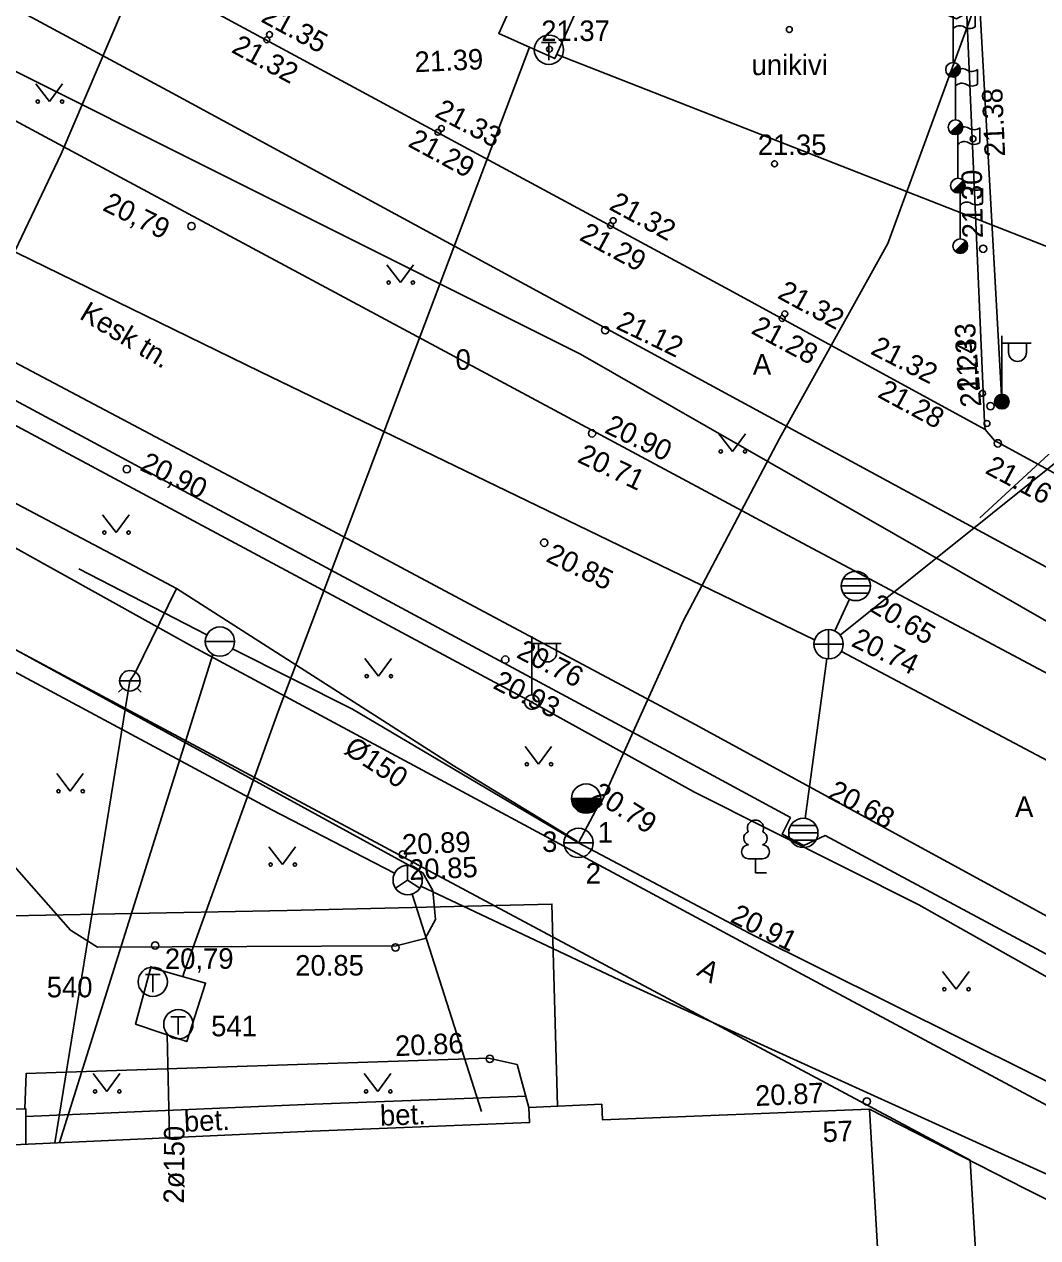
# Model space of a CAD drawing. Extents: x 714038 to 714279, y 6589845 to 6590041.
# Drawn here: x 714214.57 to 714249.16, y 6589892.78 to 6589934.18 of the extents above; entities that cross this region are included whole.
import ezdxf

# ---------------------------------------------------------------- set-up
doc = ezdxf.new("R2010")
doc.units = 0
for name, color, linetype in [('HALJASTUS', 7, 'Continuous'), ('HOONE', 7, 'Continuous'), ('HOONEDET', 7, 'Continuous'), ('KKAEV', 7, 'Continuous'), ('KORGUS', 7, 'Continuous'), ('KPKAABEL', 7, 'Continuous'), ('MPKAABEL', 7, 'Continuous'), ('POST', 7, 'Continuous'), ('PUU', 7, 'Continuous'), ('RAJATIS', 7, 'Continuous'), ('SIKAEV', 7, 'Continuous'), ('SITRASS', 7, 'Continuous'), ('SKKAEV', 7, 'Continuous'), ('SKTRASS', 7, 'Continuous'), ('TEE', 7, 'Continuous'), ('TKAEV', 7, 'Continuous'), ('TORU NR', 7, 'Continuous'), ('TTRASS', 7, 'Continuous'), ('VKAEV', 7, 'Continuous'), ('VTRASS', 7, 'Continuous'), ('Слой 1', 7, 'Continuous')]:
    doc.layers.add(name, color=color, linetype=linetype)

msp = doc.modelspace()

# ---------------------------------------------------------------- linework, layer by layer
at = {"layer": 'HALJASTUS'}
for p, q in [((714214.971, 6589932.147), (714215.434, 6589931.54)), ((714215.434, 6589931.54), (714215.88, 6589932.147)), ((714226.945, 6589925.973), (714227.409, 6589925.366)), ((714227.409, 6589925.366), (714227.854, 6589925.973)), ((714238.28, 6589920.21), (714238.744, 6589919.603)), ((714238.744, 6589919.603), (714239.189, 6589920.21)), ((714217.242, 6589917.442), (714217.706, 6589916.836)), ((714217.706, 6589916.836), (714218.151, 6589917.442)), ((714226.198, 6589912.544), (714226.661, 6589911.937)), ((714226.661, 6589911.937), (714227.107, 6589912.544)), ((714231.662, 6589909.537), (714232.126, 6589908.931)), ((714232.126, 6589908.931), (714232.571, 6589909.537)), ((714215.678, 6589908.619), (714216.141, 6589908.012)), ((714216.141, 6589908.012), (714216.587, 6589908.619)), ((714222.917, 6589906.115), (714223.381, 6589905.508)), ((714223.381, 6589905.508), (714223.826, 6589906.115)), ((714245.911, 6589901.864), (714246.374, 6589901.257)), ((714246.374, 6589901.257), (714246.819, 6589901.864)), ((714216.927, 6589898.377), (714217.39, 6589897.77)), ((714217.39, 6589897.77), (714217.836, 6589898.377)), ((714226.176, 6589898.377), (714226.64, 6589897.77)), ((714226.64, 6589897.77), (714227.085, 6589898.377))]:
    msp.add_line(p, q, dxfattribs=at)
for centre in [(714215.033, 6589931.54), (714215.862, 6589931.54), (714227.008, 6589925.366), (714227.837, 6589925.366), (714238.343, 6589919.603), (714239.172, 6589919.603), (714217.305, 6589916.836), (714218.133, 6589916.836), (714226.26, 6589911.937), (714227.089, 6589911.937), (714231.725, 6589908.931), (714232.554, 6589908.931), (714215.74, 6589908.012), (714216.569, 6589908.012), (714222.98, 6589905.508), (714223.808, 6589905.508), (714245.973, 6589901.257), (714246.802, 6589901.257), (714216.989, 6589897.77), (714217.818, 6589897.77), (714226.239, 6589897.77), (714227.067, 6589897.77)]:
    msp.add_circle(centre, 0.055, dxfattribs=at)
at = {"layer": 'HOONE'}
for points in [[(714037.81, 6590017.576), (714059.08, 6590006.51), (714072.38, 6589999.69), (714082.14, 6589994.37), (714104.85, 6589981.96), (714150.21, 6589957.43), (714183.55, 6589939.45), (714202.68, 6589928.99), (714214.04, 6589922.75), (714222.92, 6589918.06), (714237.47, 6589910.29), (714252.27, 6589902.23), (714256.602, 6589899.815), (714258.577, 6589898.715), (714261.69, 6589896.98)], [(714232.775, 6589897.266), (714232.58, 6589904.16), (714223.55, 6589903.94), (714211.77, 6589903.72), (714206.52, 6589903.61), (714195.92, 6589923.31), (714175.53, 6589922.39), (714175.7, 6589917.845), (714175.811, 6589914.882), (714176.08, 6589907.69)], [(714224.4, 6589896.416), (714231.818, 6589896.708), (714231.798, 6589897.222), (714234.283, 6589897.334), (714234.304, 6589896.805), (714243.421, 6589897.164), (714244.031, 6589886.542), (714224.36, 6589885.65), (714203.25, 6589884.69), (714202.77, 6589895.43), (714224.4, 6589896.416)]]:
    msp.add_lwpolyline(points, dxfattribs=at)
at = {"layer": 'HOONEDET'}
for points in [[(714214.63, 6589896.91), (714224.16, 6589897.321), (714231.692, 6589897.611)], [(714214.63, 6589895.98), (714214.63, 6589897.17), (714211.6, 6589897.12), (714211.69, 6589895.84)]]:
    msp.add_lwpolyline(points, dxfattribs=at)
at = {"layer": 'KKAEV'}
for p, q in [((714242.025, 6589912.527), (714242.025, 6589913.527)), ((714241.525, 6589913.027), (714242.525, 6589913.027))]:
    msp.add_line(p, q, dxfattribs=at)
msp.add_circle((714242.025, 6589913.027), 0.5, dxfattribs=at)
at = {"layer": 'KORGUS'}
for centre, radius in [((714240.683, 6589933.996), 0.1), ((714222.849, 6589933.644), 0.1), ((714222.94, 6589933.825), 0.1), ((714232.5, 6589933.327), 0.1), ((714228.808, 6589930.621), 0.1), ((714228.692, 6589930.492), 0.1), ((714246.953, 6589930.268), 0.1), ((714240.179, 6589929.419), 0.1), ((714220.28, 6589927.29), 0.125), ((714234.583, 6589927.315), 0.1), ((714234.674, 6589927.477), 0.1), ((714247.3, 6589926.52), 0.125), ((714240.437, 6589924.138), 0.1), ((714240.528, 6589924.3), 0.1), ((714234.4, 6589923.74), 0.125), ((714247.279, 6589921.586), 0.1), ((714247.55, 6589921.15), 0.125), ((714247.429, 6589920.558), 0.1), ((714233.95, 6589920.22), 0.125), ((714247.8, 6589919.88), 0.125), ((714218.07, 6589919), 0.125), ((714232.32, 6589916.49), 0.125), ((714230.99, 6589912.5), 0.125), ((714227.49, 6589905.85), 0.125), ((714219.04, 6589902.75), 0.125), ((714227.24, 6589902.68), 0.125), ((714230.46, 6589898.88), 0.125), ((714243.33, 6589897.43), 0.125)]:
    msp.add_circle(centre, radius, dxfattribs=at)
at = {"layer": 'KPKAABEL'}
msp.add_lwpolyline([(714278.95, 6590013.083), (714274.696, 6590002.154), (714268.806, 6589986.746), (714264.689, 6589977.209), (714260.118, 6589965.851), (714258.032, 6589961.24), (714253.05, 6589949.372), (714248.466, 6589938.096), (714247.531, 6589934.989), (714246.389, 6589934.367), (714239.483, 6589937.254), (714226.492, 6589940.819), (714222.669, 6589940.979), (714220.982, 6589941.049), (714220.257, 6589940.365), (714218.76, 6589936.611), (714215.836, 6589929.757), (714212.225, 6589922.206), (714208.098, 6589916.26), (714202.344, 6589907.69)], dxfattribs=at)
at = {"layer": 'MPKAABEL'}
for points in [[(714167.029, 6589999.261), (714167.805, 6589985.535), (714167.801, 6589985.524), (714168.701, 6589969.69), (714168.856, 6589964.517), (714181.003, 6589963.765), (714182.873, 6589963.649), (714187.834, 6589963.342), (714201.122, 6589963.986), (714214.138, 6589964.636), (714217.634, 6589964.759), (714217.843, 6589958.743), (714218.335, 6589947.958), (714218.782, 6589937.076), (714219.871, 6589937.206), (714226.57, 6589937.936), (714228.214, 6589938.132), (714236.763, 6589938.683), (714246.845, 6589940.926), (714247.938, 6589921.303)], [(714215.066, 6589943.967), (714214.846, 6589942.32), (714213.494, 6589938.395), (714212.085, 6589935.688), (714211.383, 6589934.84), (714211.278, 6589934.105), (714212.162, 6589933.623), (714233.552, 6589922.923), (714249.701, 6589913.675), (714250.295, 6589914.005), (714250.521, 6589914.785), (714251.05, 6589918.335), (714251.513, 6589923.366), (714251.481, 6589924.441), (714250.114, 6589927.476), (714252.56, 6589933.122), (714254.403, 6589936.762), (714260.237, 6589952.896), (714261.787, 6589959.195)], [(714231.9, 6589911.052), (714205.454, 6589925.211)], [(714231.9, 6589911.052), (714237.45, 6589907.982), (714245.1, 6589904.132), (714257.12, 6589897.374), (714259.08, 6589896.4)]]:
    msp.add_lwpolyline(points, dxfattribs=at)
at = {"layer": 'POST'}
for p, q in [((714246.095, 6589932.449), (714246.449, 6589932.802)), ((714246.178, 6589930.486), (714246.532, 6589930.839)), ((714246.26, 6589928.497), (714246.614, 6589928.85)), ((714246.341, 6589926.432), (714246.695, 6589926.785)), ((714247.938, 6589921.553), (714247.938, 6589923.553)), ((714247.938, 6589923.303), (714248.938, 6589923.303)), ((714248.165, 6589922.982), (714248.165, 6589923.303)), ((714248.778, 6589922.982), (714248.778, 6589923.303)), ((714231.9, 6589911.302), (714231.9, 6589913.302)), ((714231.9, 6589913.052), (714232.9, 6589913.052)), ((714232.127, 6589912.731), (714232.127, 6589913.052)), ((714232.74, 6589912.731), (714232.74, 6589913.052))]:
    msp.add_line(p, q, dxfattribs=at)
for centre, radius in [((714246.272, 6589932.625), 0.25), ((714246.355, 6589930.662), 0.25), ((714246.437, 6589928.673), 0.25), ((714246.518, 6589926.608), 0.25), ((714247.938, 6589921.303), 0.25), ((714247.938, 6589921.303), 0.225), ((714247.938, 6589921.303), 0.2), ((714247.938, 6589921.303), 0.175), ((714247.938, 6589921.303), 0.15), ((714247.938, 6589921.303), 0.125), ((714247.938, 6589921.303), 0.1), ((714247.938, 6589921.303), 0.075), ((714247.938, 6589921.303), 0.05), ((714247.938, 6589921.303), 0.025), ((714231.9, 6589911.052), 0.25), ((714231.9, 6589911.052), 0.0234)]:
    msp.add_circle(centre, radius, dxfattribs=at)
for centre, radius, start, end in [((714246.272, 6589932.625), 0.225, 224.8541, 45.0356), ((714246.272, 6589932.625), 0.2, 224.8427, 45.047), ((714246.272, 6589932.625), 0.175, 224.8281, 45.0616), ((714246.272, 6589932.625), 0.15, 224.8087, 45.081), ((714246.272, 6589932.625), 0.125, 224.7814, 45.1083), ((714246.272, 6589932.625), 0.1, 224.7406, 45.1491), ((714246.272, 6589932.625), 0.075, 224.6725, 45.2172), ((714246.272, 6589932.625), 0.05, 224.5363, 45.3534), ((714246.272, 6589932.625), 0.025, 224.1278, 45.7619), ((714246.355, 6589930.662), 0.225, 224.8541, 45.0356), ((714246.355, 6589930.662), 0.2, 224.8427, 45.047), ((714246.355, 6589930.662), 0.175, 224.8281, 45.0616), ((714246.355, 6589930.662), 0.15, 224.8087, 45.081), ((714246.355, 6589930.662), 0.125, 224.7814, 45.1083), ((714246.355, 6589930.662), 0.1, 224.7406, 45.1491), ((714246.355, 6589930.662), 0.075, 224.6725, 45.2172), ((714246.355, 6589930.662), 0.05, 224.5363, 45.3534), ((714246.355, 6589930.662), 0.025, 224.1278, 45.7619), ((714246.437, 6589928.673), 0.225, 224.8541, 45.0356), ((714246.437, 6589928.673), 0.2, 224.8427, 45.047), ((714246.437, 6589928.673), 0.175, 224.8281, 45.0616), ((714246.437, 6589928.673), 0.15, 224.8087, 45.081), ((714246.437, 6589928.673), 0.125, 224.7814, 45.1083), ((714246.437, 6589928.673), 0.1, 224.7406, 45.1491), ((714246.437, 6589928.673), 0.075, 224.6725, 45.2172), ((714246.437, 6589928.673), 0.05, 224.5363, 45.3534), ((714246.437, 6589928.673), 0.025, 224.1278, 45.7619), ((714246.518, 6589926.608), 0.225, 224.8541, 45.0356), ((714246.518, 6589926.608), 0.2, 224.8427, 45.047), ((714246.518, 6589926.608), 0.175, 224.8281, 45.0616), ((714246.518, 6589926.608), 0.15, 224.8087, 45.081), ((714246.518, 6589926.608), 0.125, 224.7814, 45.1083), ((714246.518, 6589926.608), 0.1, 224.7406, 45.1491), ((714246.518, 6589926.608), 0.075, 224.6725, 45.2172), ((714246.518, 6589926.608), 0.05, 224.5363, 45.3534), ((714246.518, 6589926.608), 0.025, 224.1278, 45.7619), ((714248.471, 6589922.982), 0.306, 180, 0), ((714232.434, 6589912.731), 0.306, 180, 0)]:
    msp.add_arc(centre, radius, start, end, dxfattribs=at)
at = {"layer": 'PUU'}
for p, q in [((714239.768, 6589905.707), (714239.288, 6589905.707)), ((714239.528, 6589905.232), (714239.528, 6589905.707)), ((714239.908, 6589905.232), (714239.528, 6589905.232))]:
    msp.add_line(p, q, dxfattribs=at)
for centre, radius, start, end in [((714239.528, 6589906.752), 0.277, 332.5799, 207.4201), ((714239.358, 6589906.404), 0.233, 109.0217, 253.1415), ((714239.698, 6589906.404), 0.233, 286.8508, 70.9859), ((714239.29, 6589905.944), 0.238, 90.0016, 269.3953), ((714239.765, 6589905.944), 0.238, 270.6047, 89.9984)]:
    msp.add_arc(centre, radius, start, end, dxfattribs=at)
at = {"layer": 'RAJATIS'}
for p, q in [((714246.272, 6589932.875), (714246.272, 6589934.625)), ((714247.025, 6589934.594), (714247.025, 6589934.094)), ((714246.355, 6589930.912), (714246.355, 6589932.662)), ((714247.108, 6589932.631), (714247.108, 6589932.131)), ((714246.437, 6589928.923), (714246.437, 6589930.673)), ((714247.19, 6589930.642), (714247.19, 6589930.142)), ((714246.518, 6589926.858), (714246.518, 6589928.608)), ((714247.271, 6589928.577), (714247.271, 6589928.077))]:
    msp.add_line(p, q, dxfattribs=at)
msp.add_lwpolyline([(714231.588, 6589935.687), (714233.5, 6589934.828), (714232.68, 6589933.004), (714230.768, 6589933.863)], close=True, dxfattribs=at)
for centre, radius, start, end in [((714246.495, 6589933.841), 0.288, 57.8941, 140.7366), ((714246.829, 6589934.373), 0.341, 237.8941, 305.0219), ((714246.578, 6589932.378), 0.288, 57.8941, 140.7366), ((714246.912, 6589932.91), 0.341, 237.8941, 305.0219), ((714246.578, 6589931.878), 0.288, 57.8941, 140.7366), ((714246.912, 6589932.41), 0.341, 237.8941, 305.0219), ((714246.66, 6589930.389), 0.288, 57.8941, 140.7366), ((714246.994, 6589930.921), 0.341, 237.8941, 305.0219), ((714246.66, 6589929.889), 0.288, 57.8941, 140.7366), ((714246.994, 6589930.421), 0.341, 237.8941, 305.0219), ((714246.741, 6589928.324), 0.288, 57.8941, 140.7366), ((714247.076, 6589928.856), 0.341, 237.8941, 305.0219), ((714246.741, 6589927.824), 0.288, 57.8941, 140.7366), ((714247.076, 6589928.356), 0.341, 237.8941, 305.0219)]:
    msp.add_arc(centre, radius, start, end, dxfattribs=at)
at = {"layer": 'SIKAEV'}
for p, q in [((714227.657, 6589905.482), (714227.657, 6589904.982)), ((714227.657, 6589904.982), (714227.242, 6589904.707)), ((714227.657, 6589904.982), (714228.072, 6589904.707))]:
    msp.add_line(p, q, dxfattribs=at)
msp.add_circle((714227.657, 6589904.982), 0.5, dxfattribs=at)
at = {"layer": 'SITRASS'}
for points in [[(714227.213, 6589905.211), (714223.017, 6589907.372), (714207.091, 6589915.92), (714188.911, 6589925.93), (714174.372, 6589933.714)], [(714228.11, 6589904.769), (714235.097, 6589901.472), (714246.809, 6589896.155), (714249.743, 6589894.816), (714250.57, 6589894.44), (714264.7, 6589888.06), (714272.32, 6589884.65)], [(714227.809, 6589904.505), (714230.172, 6589897.083)]]:
    msp.add_lwpolyline(points, dxfattribs=at)
at = {"layer": 'SKKAEV'}
for p, q in [((714242.453, 6589915.013), (714243.453, 6589915.013)), ((714243.383, 6589915.263), (714242.523, 6589915.263)), ((714243.383, 6589914.763), (714242.523, 6589914.763)), ((714241.591, 6589906.84), (714240.731, 6589906.84)), ((714240.661, 6589906.59), (714241.661, 6589906.59)), ((714241.591, 6589906.34), (714240.731, 6589906.34))]:
    msp.add_line(p, q, dxfattribs=at)
for centre in [(714242.953, 6589915.013), (714241.161, 6589906.59)]:
    msp.add_circle(centre, 0.5, dxfattribs=at)
at = {"layer": 'SKTRASS'}
for points in [[(714242.415, 6589913.339), (714255.39, 6589923.72), (714264.171, 6589931.743)], [(714204.551, 6589931.144), (714222.61, 6589922.33), (714241.548, 6589913.176), (714241.548, 6589913.176)], [(714247.18, 6589917.34), (714253.06, 6589922.75), (714259.876, 6589929.158)], [(714242.741, 6589914.56), (714242.237, 6589913.48)], [(714241.958, 6589912.531), (714241.228, 6589907.086)], [(714278.95, 6589894.02), (714269.47, 6589898.47), (714242.461, 6589912.782)]]:
    msp.add_lwpolyline(points, dxfattribs=at)
at = {"layer": 'TEE'}
for points in [[(714263.275, 6589906.612), (714262.481, 6589906.156), (714261.368, 6589906.05), (714260.213, 6589906.315), (714240.788, 6589916.652), (714217.995, 6589928.881), (714199.241, 6589938.974), (714197.452, 6589940.713), (714195.768, 6589942.431), (714184.455, 6589948.554)], [(714263.275, 6589906.612), (714263.414, 6589907.94), (714262.577, 6589908.551), (714241.037, 6589920.211), (714219.611, 6589931.838), (714198.955, 6589942.945), (714197.611, 6589943.352), (714197.847, 6589943.789), (714196.868, 6589944.026)], [(714217.759, 6589936.392), (714238.65, 6589925.109), (714247.372, 6589920.348), (714247.69, 6589919.978), (714264.11, 6589911.01), (714265.191, 6589911.398), (714265.199, 6589917.222), (714265.151, 6589925.259), (714246.63, 6589937.111), (714247.349, 6589920.604), (714247.372, 6589920.348)], [(714260.872, 6589896.331), (714241.905, 6589906.497), (714241.183, 6589906.16), (714240.441, 6589906.543), (714240.721, 6589907.111), (714236.852, 6589909.204), (714214.108, 6589921.428), (714203.766, 6589926.993), (714202.202, 6589927.469), (714201.413, 6589927.345), (714200.699, 6589926.934), (714199.125, 6589924.726), (714220.312, 6589912.945), (714241.895, 6589901.346), (714256.945, 6589893.296)], [(714228.18, 6589905.231), (714207.986, 6589916.277), (714199.093, 6589921.068), (714198.639, 6589920.168), (714199.213, 6589910.066), (714200.697, 6589907.311), (714202.103, 6589905.776), (714203.2, 6589905.324), (714213.313, 6589905.801), (714214.147, 6589905.548), (714216.152, 6589903.272), (714217.072, 6589902.693), (714227.265, 6589902.742), (714228.249, 6589902.983)], [(714228.249, 6589902.983), (714228.605, 6589903.639), (714228.517, 6589904.627), (714228.18, 6589905.231)], [(714214.59, 6589897.17), (714214.637, 6589898.38), (714230.412, 6589898.909), (714231.399, 6589898.684)], [(714231.399, 6589898.684), (714231.798, 6589897.222)], [(714263.472, 6589878.412), (714265.767, 6589878.509), (714265.522, 6589885.849), (714264.63, 6589886.315), (714264.168, 6589886.556), (714263.52, 6589886.894), (714261.567, 6589887.913), (714261.242, 6589888.082), (714254.879, 6589891.188), (714249.398, 6589894.111), (714248.724, 6589894.462), (714243.421, 6589897.164)]]:
    msp.add_lwpolyline(points, dxfattribs=at)
at = {"layer": 'TKAEV'}
for p, q in [((714232.228, 6589933.557), (714232.728, 6589933.557)), ((714232.478, 6589932.957), (714232.478, 6589933.557)), ((714218.71, 6589901.76), (714219.21, 6589901.76)), ((714218.96, 6589901.16), (714218.96, 6589901.76)), ((714219.58, 6589900.31), (714220.08, 6589900.31)), ((714219.83, 6589899.71), (714219.83, 6589900.31))]:
    msp.add_line(p, q, dxfattribs=at)
for centre in [(714232.478, 6589933.307), (714218.96, 6589901.51), (714219.83, 6589900.06)]:
    msp.add_circle(centre, 0.5, dxfattribs=at)
at = {"layer": 'TTRASS'}
for points in [[(714232.746, 6589933.149), (714263.03, 6589921.28), (714267.83, 6589934.38), (714270.013, 6589934.171), (714270.776, 6589934.097), (714278.95, 6589933.313)], [(714220.032, 6589901.833), (714223.24, 6589910.73), (714231.811, 6589933.394)], [(714218.89, 6589902), (714220.76, 6589901.46), (714220.12, 6589899.47), (714218.37, 6589900.06), (714218.9, 6589902.04)], [(714219.98, 6589901.69), (714220.032, 6589901.833)], [(714219.53, 6589896.2), (714219.45, 6589899.7)]]:
    msp.add_lwpolyline(points, dxfattribs=at)
at = {"layer": 'VKAEV'}
for p, q in [((714220.75, 6589913.116), (714221.75, 6589913.116)), ((714217.828, 6589911.78), (714218.528, 6589911.78)), ((714217.931, 6589911.533), (714217.791, 6589911.393)), ((714218.425, 6589911.533), (714218.565, 6589911.393)), ((714233.247, 6589907.759), (714234.247, 6589907.759)), ((714232.988, 6589906.247), (714233.988, 6589906.247))]:
    msp.add_line(p, q, dxfattribs=at)
for centre, radius in [((714221.25, 6589913.116), 0.5), ((714218.178, 6589911.78), 0.35), ((714233.747, 6589907.759), 0.5), ((714233.488, 6589906.247), 0.5)]:
    msp.add_circle(centre, radius, dxfattribs=at)
for radius in [0.483, 0.468, 0.45, 0.435, 0.418, 0.403, 0.386, 0.371, 0.354, 0.339, 0.321, 0.306, 0.289, 0.274, 0.257, 0.242, 0.224, 0.209, 0.192, 0.177, 0.16, 0.145, 0.127, 0.112, 0.0951, 0.0801, 0.0628, 0.0478, 0.0328, 0.0178]:
    msp.add_arc((714233.747, 6589907.759), radius, 180, 0, dxfattribs=at)
at = {"layer": 'VTRASS'}
for p, q in [((714218.178, 6589911.78), (714215.613, 6589896.015)), ((714234.193, 6589907.469), (714233.69, 6589907.777))]:
    msp.add_line(p, q, dxfattribs=at)
for points in [[(714234.193, 6589907.469), (714237.059, 6589913.816), (714240.349, 6589920.042), (714244.05, 6589926.694), (714247.419, 6589935.922), (714252.894, 6589948.5), (714258.093, 6589959.582), (714259.692, 6589963.065), (714262.845, 6589969.359)], [(714219.771, 6589914.924), (714218.336, 6589915.691), (714204.329, 6589923.078), (714196.383, 6589927.305), (714185.655, 6589933.263), (714178.705, 6589937.104), (714170.033, 6589941.737), (714162.674, 6589944.874), (714154.781, 6589949.135), (714153.798, 6589949.498)], [(714216.44, 6589915.593), (714220.805, 6589913.345)], [(714219.771, 6589914.924), (714218.362, 6589912.045), (714218.178, 6589911.78)], [(714219.771, 6589914.924), (714229.215, 6589908.89), (714233.438, 6589906.305)], [(714215.778, 6589896.023), (714221.01, 6589912.676), (714221.01, 6589912.677)], [(714221.682, 6589912.866), (714221.682, 6589912.866), (714225.77, 6589910.806), (714233.488, 6589906.247)], [(714233.747, 6589907.759), (714234.168, 6589907.537), (714233.488, 6589906.247)], [(714233.488, 6589906.247), (714239.337, 6589903.162), (714263.403, 6589891.181), (714275.749, 6589884.323), (714275.315, 6589880.416), (714276.224, 6589845.18)]]:
    msp.add_lwpolyline(points, dxfattribs=at)
at = {"layer": 'Слой 1'}
msp.add_lwpolyline([(714246.86, 6589895.42), (714247.69, 6589881.35), (714196.91, 6589879.78), (714193.95, 6589923.69)], close=True, dxfattribs=at)

# ---------------------------------------------------------------- texts
at = {"layer": 'HOONE'}
msp.add_text('57', height=0.7, rotation=2.582, dxfattribs=at).set_placement((714241.832, 6589896.035))
at = {"layer": 'HOONEDET'}
msp.add_text('bet.', height=0.7, rotation=2.2172, dxfattribs=at).set_placement((714226.725, 6589896.595))
at = {"layer": 'KORGUS'}
for s, rotation, p in [(' 21.35', 331.4612, (714222.384, 6589934.411)), (' 21.32', 331.6409, (714221.38, 6589933.362)), ('21.39', 2.5582, (714227.91, 6589932.54)), (' 21.38', 92.5441, (714248.064, 6589929.409)), (' 21.33', 332.1233, (714228.318, 6589931.165)), (' 21.29', 331.4894, (714227.404, 6589930.156)), ('21.30', 90.849, (714247.29, 6589926.88)), ('20,79', 334.0139, (714217.208, 6589927.847)), (' 21.32', 331.4871, (714234.266, 6589928.004)), (' 21.29', 331.5038, (714233.254, 6589926.958)), (' 21.32', 331.3647, (714240.015, 6589924.982)), ('21.12', 334.1771, (714234.73, 6589923.81)), (' 21.28', 331.7421, (714239.114, 6589923.775)), (' 21.33', 92.5441, (714247.139, 6589921.396)), (' 21.32', 332.8401, (714243.188, 6589923.068)), ('21.24', 94.6979, (714247.24, 6589921.14)), (' 21.28', 331.4225, (714243.431, 6589921.602)), ('20.90', 334.4737, (714234.34, 6589920.26)), ('20,90', 334.0139, (714218.484, 6589918.984)), ('20.71', 334.4737, (714233.41, 6589919.26)), ('21.16', 331.8458, (714247.33, 6589918.88)), ('20.85', 334.1529, (714232.34, 6589915.87)), ('20.65', 328.8545, (714243.38, 6589914.19)), ('20.74', 334.368, (714242.76, 6589912.98)), ('20.76', 333.1881, (714231.33, 6589912.59)), ('20.93', 333.1881, (714230.53, 6589911.54)), ('20.68', 332.2025, (714241.96, 6589907.8)), ('20.79', 327.9704, (714233.88, 6589907.77)), ('20.89', 2.5582, (714227.48, 6589905.84)), ('20.85', 2.5582, (714227.72, 6589904.98)), ('20.91', 333.2544, (714238.63, 6589903.57)), ('20,79', 0.2279, (714219.374, 6589901.946)), ('20.85', 0.0677, (714223.82, 6589901.72)), ('20.86', 2.5582, (714227.24, 6589898.97)), ('20.87', 2.5582, (714239.53, 6589897.27))]:
    msp.add_text(s, height=0.7, rotation=rotation, dxfattribs=at).set_placement(p)
for s, p in [(' 21.37', (714231.956, 6589933.606)), (' 21.35', (714239.347, 6589929.717)), (' 0 ', (714229.032, 6589922.388))]:
    msp.add_text(s, height=0.7, dxfattribs=at).set_placement(p)
at = {"layer": 'SIKAEV'}
for s, p in [('540', (714215.34, 6589900.98)), ('541', (714220.95, 6589899.65))]:
    msp.add_text(s, height=0.7, dxfattribs=at).set_placement(p)
at = {"layer": 'TEE'}
for s, p in [('unikivi', (714239.395, 6589932.441)), ('A', (714239.441, 6589922.228)), ('A', (714248.387, 6589907.133))]:
    msp.add_text(s, height=0.7, dxfattribs=at).set_placement(p)
for s, rotation, p in [('Kesk tn.', 328.9329, (714216.418, 6589924.154)), ('A', 329.6419, (714237.486, 6589901.755)), ('bet.', 2.7396, (714220.037, 6589896.388))]:
    msp.add_text(s, height=0.7, rotation=rotation, dxfattribs=at).set_placement(p)
at = {"layer": 'TORU NR'}
for s, p in [('1', (714234.141, 6589906.257)), ('3', (714232.246, 6589905.94)), ('2', (714233.735, 6589904.863))]:
    msp.add_text(s, height=0.7, dxfattribs=at).set_placement(p)
msp.add_text('2ø150', height=0.7, rotation=89.5498, dxfattribs=at).set_placement((714220.022, 6589893.94))
at = {"layer": 'VTRASS'}
msp.add_text('%%c150', height=0.7, rotation=326.7131, dxfattribs=at).set_placement((714225.444, 6589909.337))

doc.saveas('drawing.dxf')
